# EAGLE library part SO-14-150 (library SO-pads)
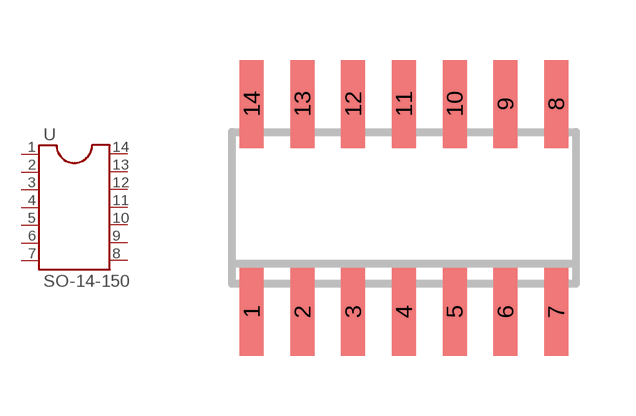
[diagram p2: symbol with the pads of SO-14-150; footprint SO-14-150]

Designator prefix -

## SO-14-150  [SO-14-150]
1  1  pas
2  2  pas
3  3  pas
4  4  pas
5  5  pas
6  6  pas
7  7  pas
8  8  pas
9  9  pas
10  10  pas
11  11  pas
12  12  pas
13  13  pas
14  14  pas

## Footprint SO-14-150 (pad centres in mm)
smd 0.6 x 2.2: 1 -3.81,-2.6; 2 -2.54,-2.6; 3 -1.27,-2.6; 4 0,-2.6; 5 1.27,-2.6; 6 2.54,-2.6; 7 3.81,-2.6; 8 3.81,2.6; 9 2.54,2.6; 10 1.27,2.6; 11 0,2.6; 12 -1.27,2.6; 13 -2.54,2.6; 14 -3.81,2.6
